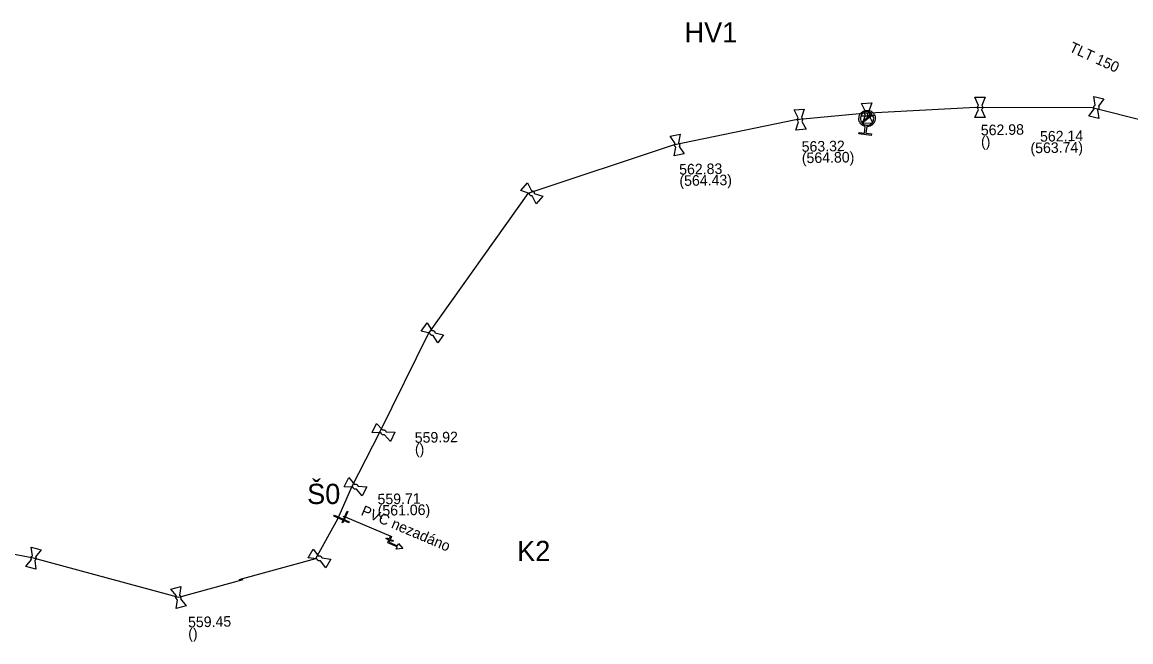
# Model space of a CAD drawing. Extents: x -643544 to -637295, y -1119190 to -1111715.
# Drawn here: x -643049.3 to -642912.6, y -1114468.5 to -1114392.1 of the extents above; entities that cross this region are included whole.
import ezdxf

# ---------------------------------------------------------------- set-up
doc = ezdxf.new("R2010")
doc.units = 0
for name, color, linetype in [('Default', 7, 'Continuous'), ('VP Hydrant', 7, 'Continuous'), ('VP Lomový bod', 7, 'Continuous'), ('VP Lomový bod - popis', 7, 'Continuous'), ('VP Popis nerozlišený', 7, 'Continuous'), ('VP Řad', 7, 'Continuous'), ('VP Řad - popis', 7, 'Continuous'), ('VP Šoupě', 7, 'Continuous')]:
    doc.layers.add(name, color=color, linetype=linetype)

msp = doc.modelspace()

# ---------------------------------------------------------------- linework, layer by layer
at = {"layer": 'Default'}
for points in [[(-642917.09, -1114402.81), (-642917.12, -1114402.77), (-642917.13, -1114402.71), (-642917.15, -1114402.63), (-642917.13, -1114402.55), (-642917.11, -1114402.47), (-642917.05, -1114402.41), (-642917.02, -1114402.37), (-642916.97, -1114402.35)], [(-642945.31, -1114404.97), (-642945.66, -1114404.9), (-642945.89, -1114404.61), (-642946.14, -1114404.28), (-642946.09, -1114403.87), (-642946.04, -1114403.46), (-642945.72, -1114403.2), (-642945.39, -1114402.95), (-642944.98, -1114403), (-642944.57, -1114403.05), (-642944.31, -1114403.37), (-642944.06, -1114403.7), (-642944.11, -1114404.11), (-642944.16, -1114404.52), (-642944.48, -1114404.78), (-642944.77, -1114405.01), (-642945.13, -1114404.99)], [(-642944.52, -1114403.42), (-642944.71, -1114403.22), (-642945, -1114403.19), (-642945.33, -1114403.14), (-642945.6, -1114403.35), (-642945.86, -1114403.56), (-642945.91, -1114403.89), (-642945.94, -1114404.18), (-642945.79, -1114404.42)], [(-642945.68, -1114404.56), (-642945.49, -1114404.76), (-642945.2, -1114404.8), (-642944.86, -1114404.84), (-642944.6, -1114404.63), (-642944.33, -1114404.43), (-642944.29, -1114404.09), (-642944.26, -1114403.8), (-642944.41, -1114403.56)], [(-642945.27, -1114403.59), (-642945.31, -1114403.56), (-642945.34, -1114403.51), (-642945.39, -1114403.44), (-642945.39, -1114403.36), (-642945.4, -1114403.27), (-642945.36, -1114403.2), (-642945.33, -1114403.15), (-642945.3, -1114403.11)], [(-642944.89, -1114403.09), (-642944.85, -1114403.12), (-642944.82, -1114403.17), (-642944.77, -1114403.24), (-642944.77, -1114403.32), (-642944.76, -1114403.41), (-642944.8, -1114403.48), (-642944.83, -1114403.53), (-642944.86, -1114403.57)], [(-642931.37, -1114402.86), (-642931.41, -1114402.82), (-642931.44, -1114402.77), (-642931.48, -1114402.7), (-642931.48, -1114402.62), (-642931.48, -1114402.54), (-642931.44, -1114402.46), (-642931.41, -1114402.42), (-642931.37, -1114402.38)], [(-642930.96, -1114402.38), (-642930.93, -1114402.42), (-642930.9, -1114402.46), (-642930.86, -1114402.54), (-642930.86, -1114402.62), (-642930.86, -1114402.7), (-642930.9, -1114402.78), (-642930.93, -1114402.82), (-642930.97, -1114402.86)], [(-642916.57, -1114402.45), (-642916.54, -1114402.49), (-642916.53, -1114402.54), (-642916.51, -1114402.63), (-642916.53, -1114402.71), (-642916.55, -1114402.79), (-642916.6, -1114402.85), (-642916.64, -1114402.89), (-642916.69, -1114402.91)], [(-642953.54, -1114404.38), (-642953.58, -1114404.34), (-642953.62, -1114404.3), (-642953.66, -1114404.23), (-642953.67, -1114404.15), (-642953.68, -1114404.07), (-642953.64, -1114403.99), (-642953.62, -1114403.94), (-642953.59, -1114403.9)], [(-642953.18, -1114403.86), (-642953.14, -1114403.89), (-642953.1, -1114403.94), (-642953.06, -1114404.01), (-642953.05, -1114404.09), (-642953.04, -1114404.17), (-642953.08, -1114404.25), (-642953.1, -1114404.3), (-642953.13, -1114404.34)], [(-642968.66, -1114407.53), (-642968.71, -1114407.51), (-642968.74, -1114407.47), (-642968.8, -1114407.4), (-642968.82, -1114407.32), (-642968.83, -1114407.24), (-642968.81, -1114407.16), (-642968.79, -1114407.11), (-642968.76, -1114407.07)], [(-642968.36, -1114406.99), (-642968.31, -1114407.01), (-642968.28, -1114407.05), (-642968.22, -1114407.12), (-642968.2, -1114407.2), (-642968.19, -1114407.28), (-642968.21, -1114407.36), (-642968.23, -1114407.41), (-642968.26, -1114407.45)], [(-642986.38, -1114413.53), (-642986.43, -1114413.54), (-642986.49, -1114413.53), (-642986.57, -1114413.51), (-642986.63, -1114413.46), (-642986.7, -1114413.4), (-642986.72, -1114413.32), (-642986.74, -1114413.27), (-642986.74, -1114413.22)], [(-642986.48, -1114412.91), (-642986.42, -1114412.9), (-642986.37, -1114412.91), (-642986.29, -1114412.93), (-642986.23, -1114412.98), (-642986.16, -1114413.04), (-642986.13, -1114413.12), (-642986.12, -1114413.17), (-642986.12, -1114413.22)], [(-642998.61, -1114430.73), (-642998.66, -1114430.75), (-642998.71, -1114430.74), (-642998.8, -1114430.73), (-642998.86, -1114430.68), (-642998.93, -1114430.64), (-642998.97, -1114430.56), (-642998.99, -1114430.51), (-642998.99, -1114430.46)], [(-642998.76, -1114430.12), (-642998.71, -1114430.11), (-642998.65, -1114430.12), (-642998.57, -1114430.13), (-642998.5, -1114430.18), (-642998.43, -1114430.22), (-642998.4, -1114430.3), (-642998.37, -1114430.35), (-642998.37, -1114430.4)], [(-643004.6, -1114442.98), (-643004.65, -1114443), (-643004.7, -1114443), (-643004.78, -1114443.01), (-643004.86, -1114442.97), (-643004.93, -1114442.93), (-643004.98, -1114442.86), (-643005.01, -1114442.82), (-643005.02, -1114442.77)], [(-643004.84, -1114442.4), (-643004.79, -1114442.38), (-643004.74, -1114442.38), (-643004.66, -1114442.37), (-643004.58, -1114442.41), (-643004.51, -1114442.45), (-643004.46, -1114442.52), (-643004.43, -1114442.56), (-643004.42, -1114442.61)], [(-643008.04, -1114449.69), (-643008.09, -1114449.71), (-643008.15, -1114449.71), (-643008.23, -1114449.72), (-643008.3, -1114449.68), (-643008.38, -1114449.64), (-643008.42, -1114449.57), (-643008.45, -1114449.52), (-643008.46, -1114449.47)], [(-643008.28, -1114449.11), (-643008.23, -1114449.09), (-643008.18, -1114449.09), (-643008.09, -1114449.09), (-643008.02, -1114449.12), (-643007.94, -1114449.16), (-643007.9, -1114449.23), (-643007.87, -1114449.28), (-643007.86, -1114449.33)], [(-643048.12, -1114458.39), (-643048.15, -1114458.34), (-643048.16, -1114458.29), (-643048.18, -1114458.21), (-643048.16, -1114458.13), (-643048.14, -1114458.05), (-643048.08, -1114457.99), (-643048.04, -1114457.95), (-643047.99, -1114457.93)], [(-643047.6, -1114458.03), (-643047.57, -1114458.08), (-643047.56, -1114458.13), (-643047.54, -1114458.21), (-643047.56, -1114458.29), (-643047.58, -1114458.37), (-643047.64, -1114458.43), (-643047.68, -1114458.47), (-643047.72, -1114458.49)], [(-643012.5, -1114458.53), (-643012.55, -1114458.55), (-643012.61, -1114458.55), (-643012.69, -1114458.55), (-643012.76, -1114458.51), (-643012.83, -1114458.47), (-643012.88, -1114458.4), (-643012.91, -1114458.35), (-643012.92, -1114458.3)], [(-643012.72, -1114457.95), (-643012.67, -1114457.93), (-643012.61, -1114457.93), (-643012.53, -1114457.93), (-643012.46, -1114457.97), (-643012.39, -1114458.01), (-643012.34, -1114458.08), (-643012.31, -1114458.13), (-643012.3, -1114458.18)], [(-643030.12, -1114463.33), (-643030.17, -1114463.31), (-643030.21, -1114463.27), (-643030.27, -1114463.21), (-643030.29, -1114463.13), (-643030.31, -1114463.05), (-643030.29, -1114462.97), (-643030.28, -1114462.92), (-643030.25, -1114462.87)], [(-643029.86, -1114462.77), (-643029.81, -1114462.79), (-643029.77, -1114462.83), (-643029.71, -1114462.89), (-643029.69, -1114462.97), (-643029.67, -1114463.05), (-643029.69, -1114463.13), (-643029.7, -1114463.18), (-643029.73, -1114463.22)]]:
    msp.add_open_spline(points, degree=3, dxfattribs=at)
at = {"layer": 'VP Hydrant'}
for points in [[(-642945.79, -1114404.42), (-642944.52, -1114403.42)], [(-642944.41, -1114403.56), (-642945.68, -1114404.56)], [(-642945.13, -1114404.99), (-642945.23, -1114405.8), (-642944.54, -1114405.89), (-642944.57, -1114406.07), (-642946.12, -1114405.88), (-642946.09, -1114405.7), (-642945.41, -1114405.78), (-642945.31, -1114404.97)], [(-643003.93, -1114456), (-643004.03, -1114456.23), (-643002.99, -1114456.67), (-643002.87, -1114456.39), (-643002.33, -1114457.02), (-643003.16, -1114457.08), (-643003.04, -1114456.79), (-643004.19, -1114456.3), (-643004.04, -1114455.95), (-643004.39, -1114455.81), (-643004.34, -1114455.69), (-643003.99, -1114455.84), (-643003.85, -1114455.5), (-643003.73, -1114455.55), (-643003.88, -1114455.89), (-643003.54, -1114456.03), (-643003.59, -1114456.15), (-643003.93, -1114456)]]:
    msp.add_lwpolyline(points, dxfattribs=at)
at = {"layer": 'VP Lomový bod'}
for points in [[(-642945.3, -1114403.11), (-642945.77, -1114402.12), (-642944.52, -1114402.06), (-642944.89, -1114403.09)], [(-642931.79, -1114401.37), (-642930.54, -1114401.37), (-642930.96, -1114402.38)], [(-642931.37, -1114402.38), (-642931.79, -1114401.37)], [(-642917.13, -1114401.26), (-642915.92, -1114401.57), (-642916.57, -1114402.45)], [(-642916.97, -1114402.35), (-642917.13, -1114401.26)], [(-642954.1, -1114402.93), (-642952.85, -1114402.82), (-642953.18, -1114403.86)], [(-642953.59, -1114403.9), (-642954.1, -1114402.93)], [(-642944.39, -1114404.56), (-642945.64, -1114404.62), (-642945.27, -1114403.59)], [(-642944.86, -1114403.57), (-642944.39, -1114404.56)], [(-642930.97, -1114402.86), (-642930.55, -1114403.87), (-642931.8, -1114403.87), (-642931.37, -1114402.86)], [(-642916.69, -1114402.91), (-642916.53, -1114403.99), (-642917.74, -1114403.69), (-642917.09, -1114402.81)], [(-642953.13, -1114404.34), (-642952.62, -1114405.31), (-642953.86, -1114405.42), (-642953.54, -1114404.38)], [(-642969.38, -1114406.16), (-642968.15, -1114405.91), (-642968.36, -1114406.99)], [(-642968.76, -1114407.07), (-642969.38, -1114406.16)], [(-642968.26, -1114407.45), (-642967.64, -1114408.36), (-642968.87, -1114408.61), (-642968.66, -1114407.53)], [(-642986.74, -1114413.22), (-642987.78, -1114412.88), (-642986.97, -1114411.93), (-642986.48, -1114412.91)], [(-642986.12, -1114413.22), (-642985.07, -1114413.56)], [(-642985.07, -1114413.56), (-642985.89, -1114414.51), (-642986.38, -1114413.53)], [(-643000.06, -1114430.21), (-642999.34, -1114429.2), (-642998.76, -1114430.12)], [(-642998.99, -1114430.46), (-643000.06, -1114430.21)], [(-642998.37, -1114430.4), (-642997.3, -1114430.65), (-642998.02, -1114431.66), (-642998.61, -1114430.73)], [(-643006.12, -1114442.7), (-643005.56, -1114441.58), (-643004.84, -1114442.4)], [(-643005.02, -1114442.77), (-643006.12, -1114442.7)], [(-643004.42, -1114442.61), (-643003.32, -1114442.68), (-643003.87, -1114443.8), (-643004.6, -1114442.98)], [(-643009.56, -1114449.39), (-643008.99, -1114448.27), (-643008.28, -1114449.11)], [(-643008.46, -1114449.47), (-643009.56, -1114449.39)], [(-643007.86, -1114449.33), (-643006.76, -1114449.41), (-643007.33, -1114450.53), (-643008.04, -1114449.69)], [(-643048.14, -1114456.84), (-643046.93, -1114457.17), (-643047.6, -1114458.03)], [(-643047.99, -1114457.93), (-643048.14, -1114456.84)], [(-643047.72, -1114458.49), (-643047.58, -1114459.58), (-643048.79, -1114459.25), (-643048.12, -1114458.39)], [(-643014.01, -1114458.17), (-643013.39, -1114457.08), (-643012.72, -1114457.95)], [(-643012.92, -1114458.3), (-643014.01, -1114458.17)], [(-643012.3, -1114458.18), (-643011.21, -1114458.31), (-643011.83, -1114459.4), (-643012.5, -1114458.53)], [(-643030.93, -1114462.01), (-643029.72, -1114461.68), (-643029.86, -1114462.77)], [(-643030.25, -1114462.87), (-643030.93, -1114462.01)], [(-643029.73, -1114463.22), (-643029.05, -1114464.09), (-643030.26, -1114464.42), (-643030.12, -1114463.33)]]:
    msp.add_lwpolyline(points, dxfattribs=at)
at = {"layer": 'VP Řad'}
for points in [[(-642910.65, -1114404.34), (-642917.33, -1114402.66), (-642931.67, -1114402.65), (-642945.58, -1114403.37), (-642953.86, -1114404.15), (-642969.01, -1114407.29), (-642986.93, -1114413.25), (-642999.18, -1114430.46), (-643005.22, -1114442.72), (-643008.66, -1114449.43), (-643010.22, -1114453.04), (-643010.38, -1114453.4), (-643013.11, -1114458.27), (-643022.57, -1114460.89)], [(-642945.08, -1114403.34), (-642945.06, -1114403.66), (-642945.1, -1114403.99)], [(-643031, -1114462.78), (-643047.86, -1114458.21), (-643072.95, -1114453.4)], [(-643009.72, -1114453.01), (-643009.46, -1114453.12), (-643003.82, -1114455.51)], [(-643022.07, -1114460.86), (-643029.99, -1114463.05), (-643031, -1114462.78)]]:
    msp.add_lwpolyline(points, dxfattribs=at)
at = {"layer": 'VP Šoupě'}
for points in [[(-642944.31, -1114403.66), (-642945.8, -1114403.75), (-642945.81, -1114403.66), (-642944.31, -1114403.57), (-642944.31, -1114403.66)], [(-643010.77, -1114452.92), (-643008.94, -1114453.71), (-643008.99, -1114453.83), (-643010.82, -1114453.03), (-643010.77, -1114452.92)], [(-643009.12, -1114452.45), (-643009.72, -1114453.83), (-643009.8, -1114453.79), (-643009.2, -1114452.41), (-643009.12, -1114452.45)]]:
    msp.add_lwpolyline(points, dxfattribs=at)

# ---------------------------------------------------------------- texts
at = {"layer": 'VP Lomový bod - popis'}
for s, p in [('562.98', (-642931.06, -1114406.07)), ('()', (-642931.04, -1114407.47)), ('562.14', (-642923.76, -1114406.85)), ('563.32', (-642953.15, -1114408.1)), ('(563.74)', (-642924.94, -1114408.28)), ('(564.80)', (-642953.13, -1114409.5)), ('562.83', (-642968.25, -1114410.91)), ('(564.43)', (-642968.22, -1114412.31)), ('559.92', (-643000.85, -1114443.99)), ('()', (-643000.83, -1114445.39)), ('559.71', (-643005.44, -1114451.58)), ('(561.06)', (-643005.42, -1114452.98)), ('559.45', (-643028.8, -1114466.74)), ('()', (-643028.78, -1114468.14))]:
    msp.add_text(s, height=1.3, rotation=1, dxfattribs=at).set_placement(p)
at = {"layer": 'VP Popis nerozlišený'}
for s, p in [('HV1', (-642967.6, -1114394.61)), ('Š0', (-643014.13, -1114451.53)), ('K2', (-642988.24, -1114458.57))]:
    msp.add_text(s, height=2.5, dxfattribs=at).set_placement(p)
at = {"layer": 'VP Řad - popis'}
for s, rotation, p in [('TLT 150', 335.4175, (-642920.28, -1114395.67)), ('PVC nezadáno', 337.0347, (-643007.59, -1114452.85))]:
    msp.add_text(s, height=1.3, rotation=rotation, dxfattribs=at).set_placement(p)

doc.saveas('drawing.dxf')
